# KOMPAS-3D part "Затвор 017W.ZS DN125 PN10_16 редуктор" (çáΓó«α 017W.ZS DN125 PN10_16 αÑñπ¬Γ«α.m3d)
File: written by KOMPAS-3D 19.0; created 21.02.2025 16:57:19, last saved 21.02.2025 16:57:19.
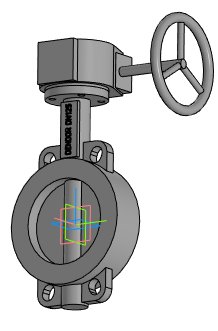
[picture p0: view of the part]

Document properties: Автор: Евгений; Полное имя файла: Затвор 017W.ZS DN125 PN10_16 редуктор.a3d

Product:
- Part/product: Затвор 017W.ZS DN125 PN10_16 редуктор
    Масса: 15.8025

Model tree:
1. Операция без истории:1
